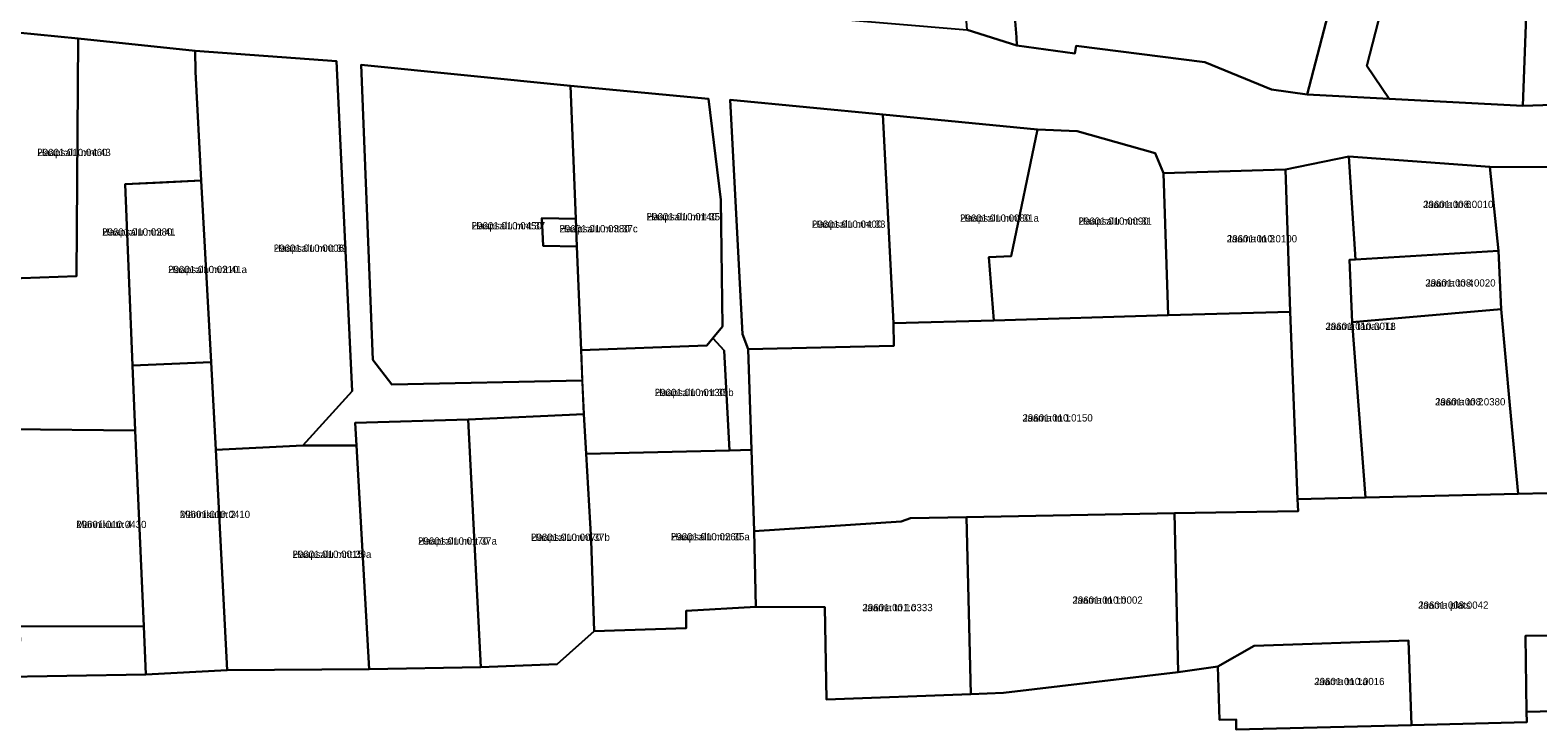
# Model space of a CAD drawing. Extents: x 518839 to 525192, y 6573164 to 6576561.
# Drawn here: x 523365.3 to 523676.7, y 6574299.5 to 6574443.2 of the extents above; entities that cross this region are included whole.
import ezdxf

# ---------------------------------------------------------------- set-up
doc = ezdxf.new("R2010")
doc.units = 0
for name, color, linetype in [('L_AADRESS', 7, 'Continuous'), ('PIIR', 7, 'Continuous'), ('TUNNUS', 7, 'Continuous')]:
    doc.layers.add(name, color=color, linetype=linetype)

msp = doc.modelspace()

# ---------------------------------------------------------------- linework, layer by layer
at = {"layer": 'PIIR'}
for points in [[(523700.2, 6574721.72), (523710.02, 6574696.46), (523687.1, 6574608.01), (523679.27, 6574581.95), (523679.09, 6574579.83), (523655.53, 6574491), (523641.32, 6574435.85), (523645.97, 6574429.03), (523629.03, 6574429.92), (523640.58, 6574474.42), (523653.58, 6574524.69), (523653.71, 6574525.12), (523656.28, 6574534.68), (523658.83, 6574544.16), (523661.39, 6574553.49), (523663.93, 6574562.87), (523666.49, 6574572.3), (523669.1, 6574581.93), (523672.63, 6574594.87), (523675.51, 6574611.76), (523672.22, 6574628.03), (523679.3, 6574630.35), (523689.46, 6574680.22)], [(523543.19, 6574637.93), (523540.34, 6574674.35), (523549.77, 6574671.85), (523551.7, 6574651.94), (523552.95, 6574634.06), (523556.48, 6574594.4), (523558.48, 6574567.15), (523560.09, 6574546.96), (523562.38, 6574526.98), (523563.91, 6574507.04), (523565.54, 6574487.01), (523566.98, 6574466.62), (523568.99, 6574441.81), (523569.1, 6574440.03), (523558.83, 6574443.32), (523557.1, 6574466.25), (523554.58, 6574498.15), (523552.58, 6574520.23), (523551.05, 6574542.17), (523548.62, 6574570.34), (523546.53, 6574594.73), (523544.14, 6574614.8)], [(523655.53, 6574491), (523675.69, 6574485.98), (523675.73, 6574485.36), (523673.58, 6574427.58), (523645.97, 6574429.03), (523641.32, 6574435.85)], [(523581.36, 6574439.99), (523581.08, 6574438.42), (523569.1, 6574440.03), (523568.99, 6574441.81), (523566.98, 6574466.62), (523599.09, 6574462.04), (523598.96, 6574476.23), (523597.61, 6574485.39), (523640.58, 6574474.42), (523629.03, 6574429.92), (523621.69, 6574430.98), (523607.89, 6574436.58)], [(523673.58, 6574427.58), (523675.73, 6574485.36), (523690.47, 6574482.07), (523690.04, 6574449.11), (523691.03, 6574449.13), (523690.95, 6574439.29), (523696.07, 6574437.5), (523696.24, 6574428.38)], [(523304.72, 6574426.21), (523304.19, 6574446.22), (523318.49, 6574447.43), (523319.75, 6574408.88), (523320.68, 6574384.72), (523321.56, 6574360.96), (523322.56, 6574336.43), (523323.36, 6574316.4), (523363.35, 6574317.07), (523363.18, 6574320.07), (523388.79, 6574320.15), (523389.23, 6574310.15), (523323.9, 6574309.05), (523264.85, 6574308.54), (523264.01, 6574332.43), (523270.83, 6574332.75), (523308.28, 6574334.49), (523307.58, 6574356.42), (523306.24, 6574386.39), (523305.44, 6574406.38)], [(523375.25, 6574441.47), (523374.88, 6574392.44), (523359.74, 6574391.88), (523359.17, 6574409.07), (523358.38, 6574443.13)], [(523399.43, 6574438.95), (523399.48, 6574434.63), (523400.69, 6574412.15), (523384.94, 6574411.42), (523386.45, 6574373.96), (523387.04, 6574360.55), (523360.93, 6574360.82), (523359.96, 6574385.13), (523359.74, 6574391.88), (523374.88, 6574392.44), (523375.25, 6574441.47)], [(523428.59, 6574436.85), (523431.86, 6574368.66), (523421.64, 6574357.42), (523403.67, 6574356.53), (523402.72, 6574374.67), (523400.69, 6574412.15), (523399.48, 6574434.63), (523399.43, 6574438.95)], [(523476.95, 6574431.75), (523478.03, 6574404.28), (523471.01, 6574404.37), (523471.25, 6574398.68), (523478.25, 6574398.57), (523479.09, 6574377.15), (523479.34, 6574370.86), (523440.05, 6574370.03), (523436.08, 6574375.15), (523433.67, 6574436.06)], [(523478.25, 6574398.57), (523478.03, 6574404.28), (523476.95, 6574431.75), (523505.39, 6574429.04), (523507.95, 6574408.21), (523508.33, 6574382.05), (523506.31, 6574379.6), (523505.07, 6574378.1), (523479.09, 6574377.15)], [(523512.44, 6574380.42), (523509.88, 6574428.84), (523541.41, 6574425.79), (523543.63, 6574382.68), (523543.68, 6574378.01), (523513.58, 6574377.32)], [(523541.41, 6574425.79), (523573.32, 6574422.69), (523567.89, 6574396.56), (523563.28, 6574396.32), (523564.32, 6574383.29), (523543.63, 6574382.68)], [(523563.28, 6574396.32), (523567.89, 6574396.56), (523573.32, 6574422.69), (523581.53, 6574422.34), (523597.62, 6574417.85), (523599.4, 6574413.71), (523600.34, 6574384.39), (523564.32, 6574383.29)], [(523624.57, 6574414.42), (523637.66, 6574417.12), (523639.01, 6574395.86), (523637.76, 6574395.79), (523638.33, 6574382.91), (523641.08, 6574346.71), (523627.04, 6574346.36), (523625.5, 6574385.07)], [(523637.66, 6574417.12), (523666.73, 6574415.03), (523668.57, 6574397.63), (523639.01, 6574395.86)], [(523668.57, 6574397.63), (523666.73, 6574415.03), (523708.75, 6574414.77), (523712.43, 6574387.75), (523721.13, 6574366.63), (523712.13, 6574365.98), (523712.47, 6574348.57), (523684.56, 6574347.77), (523672.6, 6574347.44), (523670.88, 6574365.74), (523669.08, 6574385.57)], [(523392.65, 6574411.77), (523400.69, 6574412.15), (523402.72, 6574374.67), (523386.45, 6574373.96), (523384.94, 6574411.42)], [(523599.4, 6574413.71), (523624.57, 6574414.42), (523625.5, 6574385.07), (523600.34, 6574384.39)], [(523478.03, 6574404.28), (523478.25, 6574398.57), (523471.25, 6574398.68), (523471.01, 6574404.37)], [(523637.76, 6574395.79), (523639.01, 6574395.86), (523668.57, 6574397.63), (523669.08, 6574385.57), (523638.33, 6574382.91)], [(523545.17, 6574341.76), (523514.86, 6574339.73), (523514.29, 6574356.53), (523513.58, 6574377.32), (523543.68, 6574378.01), (523543.63, 6574382.68), (523564.32, 6574383.29), (523600.34, 6574384.39), (523625.5, 6574385.07), (523627.04, 6574346.36), (523627.14, 6574343.91), (523601.66, 6574343.44), (523558.67, 6574342.64), (523547.15, 6574342.43)], [(523638.33, 6574382.91), (523669.08, 6574385.57), (523670.88, 6574365.74), (523672.6, 6574347.44), (523641.08, 6574346.71)], [(523479.67, 6574363.89), (523479.09, 6574377.15), (523505.07, 6574378.1), (523506.31, 6574379.6), (523508.62, 6574377.08), (523509.74, 6574356.42), (523480.15, 6574355.7)], [(523402.72, 6574374.67), (523403.67, 6574356.53), (523406.04, 6574311.07), (523389.23, 6574310.15), (523388.79, 6574320.15), (523387.04, 6574360.55), (523386.45, 6574373.96)], [(523432.73, 6574357.47), (523432.46, 6574362.15), (523455.76, 6574362.82), (523458.42, 6574311.69), (523435.36, 6574311.22)], [(523455.76, 6574362.82), (523479.67, 6574363.89), (523480.15, 6574355.7), (523481.21, 6574337.85), (523481.78, 6574319.1), (523474.18, 6574312.3), (523458.42, 6574311.69)], [(523362.23, 6574337.28), (523360.93, 6574360.82), (523387.04, 6574360.55), (523388.79, 6574320.15), (523363.18, 6574320.07)], [(523403.67, 6574356.53), (523421.64, 6574357.42), (523432.73, 6574357.47), (523435.36, 6574311.22), (523406.04, 6574311.07)], [(523481.21, 6574337.85), (523480.15, 6574355.7), (523509.74, 6574356.42), (523514.29, 6574356.53), (523514.86, 6574339.73), (523515.16, 6574324.11), (523500.8, 6574323.29), (523500.8, 6574319.69), (523481.78, 6574319.1)], [(523602.37, 6574310.61), (523601.66, 6574343.44), (523627.14, 6574343.91), (523627.04, 6574346.36), (523641.08, 6574346.71), (523672.6, 6574347.44), (523684.56, 6574347.77), (523694.97, 6574332.28), (523706.05, 6574318.49), (523674.12, 6574318.12), (523674.33, 6574302.46), (523674.36, 6574300.29), (523650.57, 6574299.69), (523649.98, 6574317.14), (523618.1, 6574316.06), (523610.6, 6574311.8)], [(523602.37, 6574310.61), (523566.33, 6574306.33), (523559.55, 6574306.09), (523558.67, 6574342.64), (523601.66, 6574343.44)], [(523514.86, 6574339.73), (523545.17, 6574341.76), (523547.15, 6574342.43), (523558.67, 6574342.64), (523559.55, 6574306.09), (523529.75, 6574304.96), (523529.46, 6574324.09), (523515.16, 6574324.11)], [(523702.41, 6574303.1), (523674.33, 6574302.46), (523674.12, 6574318.12), (523706.05, 6574318.49), (523707.28, 6574318.5), (523707.62, 6574306.28), (523709.45, 6574303.26), (523707.74, 6574300.22), (523704.18, 6574300.1)], [(523610.6, 6574311.8), (523618.1, 6574316.06), (523649.98, 6574317.14), (523650.57, 6574299.69), (523614.39, 6574298.78), (523614.36, 6574300.83), (523610.9, 6574300.81)]]:
    msp.add_lwpolyline(points, close=True, dxfattribs=at)
for points in [[(523353.78, 6574457.82), (523377.5, 6574455.78), (523397.99, 6574454), (523425.84, 6574451.01), (523431.9, 6574450.04), (523472.47, 6574445.83), (523477.93, 6574449.33), (523501.43, 6574447.28), (523527.59, 6574445.88), (523558.83, 6574443.32), (523569.1, 6574440.03), (523581.08, 6574438.42), (523581.36, 6574439.99), (523607.89, 6574436.58), (523621.69, 6574430.98), (523629.03, 6574429.92), (523645.97, 6574429.03), (523673.58, 6574427.58), (523696.24, 6574428.38)], [(523708.75, 6574414.77), (523666.73, 6574415.03), (523637.66, 6574417.12), (523624.57, 6574414.42), (523599.4, 6574413.71), (523597.62, 6574417.85), (523581.53, 6574422.34), (523573.32, 6574422.69), (523541.41, 6574425.79), (523509.88, 6574428.84), (523512.44, 6574380.42), (523513.58, 6574377.32), (523514.29, 6574356.53), (523509.74, 6574356.42), (523508.62, 6574377.08), (523506.31, 6574379.6), (523508.33, 6574382.05), (523507.95, 6574408.21), (523505.39, 6574429.04), (523476.95, 6574431.75), (523433.67, 6574436.06), (523436.08, 6574375.15), (523440.05, 6574370.03), (523479.34, 6574370.86), (523479.67, 6574363.89), (523455.76, 6574362.82), (523432.46, 6574362.15), (523432.73, 6574357.47), (523421.64, 6574357.42), (523431.86, 6574368.66), (523428.59, 6574436.85), (523399.43, 6574438.95), (523375.25, 6574441.47), (523358.38, 6574443.13)], [(523323.9, 6574309.05), (523389.23, 6574310.15), (523406.04, 6574311.07), (523435.36, 6574311.22), (523458.42, 6574311.69), (523474.18, 6574312.3), (523481.78, 6574319.1), (523500.8, 6574319.69), (523500.8, 6574323.29), (523515.16, 6574324.11), (523529.46, 6574324.09), (523529.75, 6574304.96), (523559.55, 6574306.09), (523566.33, 6574306.33), (523602.37, 6574310.61), (523610.6, 6574311.8), (523610.9, 6574300.81), (523614.36, 6574300.83), (523614.39, 6574298.78), (523650.57, 6574299.69), (523674.36, 6574300.29), (523674.33, 6574302.46), (523702.41, 6574303.1)]]:
    msp.add_lwpolyline(points, dxfattribs=at)

# ---------------------------------------------------------------- texts
at = {"layer": 'L_AADRESS'}
for s, p in [('Haapsalu mnt 43', (523366.82, 6574417.22)), ('Haapsalu mnt 35', (523492.64, 6574403.95)), ('Haapsalu mnt 31a', (523557.36, 6574403.66)), ('Jaama tn 6', (523652.98, 6574406.49)), ('Haapsalu mnt 41', (523380.21, 6574400.79)), ('Haapsalu mnt 37', (523456.51, 6574402.08)), ('Haapsalu mnt 37c', (523474.64, 6574401.47)), ('Haapsalu mnt 33', (523526.78, 6574402.41)), ('Haapsalu mnt 31', (523581.81, 6574403.04)), ('Haapsalu mnt 39', (523415.64, 6574397.45)), ('Jaama tn 3', (523612.45, 6574399.4)), ('Haapsalu mnt 41a', (523393.83, 6574393.05)), ('Jaama tn 4', (523653.44, 6574390.27)), ('Jaama tänav T1', (523632.82, 6574381.31)), ('Haapsalu mnt 35b', (523494.32, 6574367.65)), ('Jaama tn 2', (523655.46, 6574365.72)), ('Jaama tn 1', (523570.25, 6574362.4)), ('Männiku tn 2', (523396.25, 6574342.46)), ('Männiku tn 4', (523374.86, 6574340.39)), ('Haapsalu mnt 37a', (523445.44, 6574336.97)), ('Haapsalu mnt 37b', (523468.77, 6574337.75)), ('Haapsalu mnt 35a', (523497.65, 6574337.86)), ('Haapsalu mnt 39a', (523419.52, 6574334.23)), ('Jaama tn 1c', (523537.2, 6574323.23)), ('Jaama tn 1b', (523580.58, 6574324.77)), ('Jaama plats', (523651.96, 6574323.73)), ('Jaama tn 1a', (523630.5, 6574307.96))]:
    msp.add_text(s, height=1.5, dxfattribs=at).set_placement(p)
at = {"layer": 'TUNNUS'}
for s, p in [('29601:010:0460', (523366.82, 6574417.22)), ('29601:010:0140', (523492.64, 6574403.95)), ('29601:010:0080', (523557.36, 6574403.66)), ('29601:008:0010', (523652.98, 6574406.49)), ('29601:010:0280', (523380.21, 6574400.79)), ('29601:010:0450', (523456.51, 6574402.08)), ('29601:010:0380', (523474.64, 6574401.47)), ('29601:010:0400', (523526.78, 6574402.41)), ('29601:010:0090', (523581.81, 6574403.04)), ('29601:010:0006', (523415.64, 6574397.45)), ('29601:010:0100', (523612.45, 6574399.4)), ('29601:010:0210', (523393.83, 6574393.05)), ('29601:008:0020', (523653.44, 6574390.27)), ('29601:010:0018', (523632.82, 6574381.31)), ('29601:010:0130', (523494.32, 6574367.65)), ('29601:008:0380', (523655.46, 6574365.72)), ('29601:010:0150', (523570.25, 6574362.4)), ('29601:010:0410', (523396.25, 6574342.46)), ('29601:010:0430', (523374.86, 6574340.39)), ('29601:010:0170', (523445.44, 6574336.97)), ('29601:010:0070', (523468.77, 6574337.75)), ('29601:010:0260', (523497.65, 6574337.86)), ('29601:010:0015', (523419.52, 6574334.23)), ('29601:001:0333', (523537.2, 6574323.23)), ('29601:010:0002', (523580.58, 6574324.77)), ('29601:008:0042', (523651.96, 6574323.73)), ('29601:010:0016', (523630.5, 6574307.96))]:
    msp.add_text(s, height=1.5, dxfattribs=at).set_placement(p)

doc.saveas('drawing.dxf')
